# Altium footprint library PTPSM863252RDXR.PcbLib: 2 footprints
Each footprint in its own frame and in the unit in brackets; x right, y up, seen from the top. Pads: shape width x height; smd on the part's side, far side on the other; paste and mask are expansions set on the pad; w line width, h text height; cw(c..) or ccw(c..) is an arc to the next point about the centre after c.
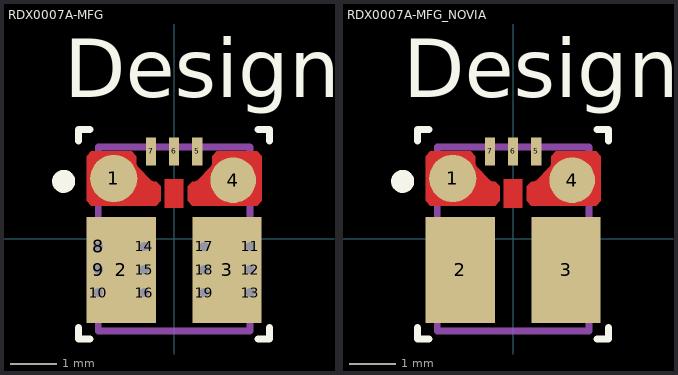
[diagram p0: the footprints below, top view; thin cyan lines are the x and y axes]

## RDX0007A-MFG [mm]
pads (19):
  round 1.025 smd paste-0.5 mask-0.495: 1(-1.312,1.312)
  rect 1.5x2.3 smd paste-1.137 mask-1.143: 2(-1.15,-0.675) 3(1.15,-0.675)
  round 0.991 smd paste-0.483 mask-0.483: 4(1.281,1.276)
  rect 0.22x0.6 smd paste+0 mask-0.292: 5(0.5,1.9) 6(0,1.9) 7(-0.5,1.9)
  round 0.5 hole 0.203 paste-0.25 mask-0.241: 8(-1.65,-0.165) 9(-1.65,-0.665) 10(-1.65,-1.165) 11(1.65,-0.165) 12(1.65,-0.665) 13(1.65,-1.165) 14(-0.65,-0.165) 15(-0.65,-0.665) 16(-0.65,-1.165) 17(0.65,-0.165) 18(0.65,-0.665) 19(0.65,-1.165)
Top Layer:
  region: -0.2,1.295 -0.2,0.675 0.2,0.675 0.2,1.295
  region: 1.9,0.825 1.9,1.8 1.8,1.9 0.925,1.9 0.825,1.8 0.825,1.634 0.796,1.563 0.507,1.274 0.436,1.245 0.39,1.245 0.29,1.145 0.29,0.825 0.39,0.725 1.8,0.725
  region: -1.9,0.825 -1.9,1.8 -1.8,1.9 -0.925,1.9 -0.825,1.8 -0.825,1.634 -0.796,1.563 -0.507,1.274 -0.436,1.245 -0.39,1.245 -0.29,1.145 -0.29,0.825 -0.39,0.725 -1.8,0.725
Top Overlay:
  circle w0.25: c-2.4,1.25 r0.125
  lines w0.15: -2.075,-1.925 -2.075,-2.175 -1.825,-2.175 ; -2.075,2.125 -2.075,2.375 -1.825,2.375 ; 1.825,-2.175 2.075,-2.175 2.075,-1.925 ; 1.825,2.375 2.075,2.375 2.075,2.125
  text "Designator1027" at -2.388,3.073 h1.27
  text ".Designator" at -3.492,-0.635 h1.27
Top Paste:
  drawing of 8 lines, arcs and shapes, not listed
Top Solder:
  drawing of 7 lines, arcs and shapes, not listed
Mechanical 13:
  lines w0.15: -1.65,-2 -1.65,2 1.65,2 1.65,-2 -1.65,-2
  text ".Designator" at -3.492,-0.635 h1.27

## RDX0007A-MFG_NOVIA [mm]
pads (7):
  round 1.025 smd paste-0.5 mask-0.495: 1(-1.312,1.312)
  rect 1.5x2.3 smd paste-1.137 mask-1.143: 2(-1.15,-0.675) 3(1.15,-0.675)
  round 0.991 smd paste-0.483 mask-0.483: 4(1.281,1.276)
  rect 0.22x0.6 smd paste+0 mask-0.292: 5(0.5,1.9) 6(0,1.9) 7(-0.5,1.9)
Top Layer:
  region: -0.2,1.295 -0.2,0.675 0.2,0.675 0.2,1.295
  region: -1.9,0.825 -1.9,1.8 -1.8,1.9 -0.925,1.9 -0.825,1.8 -0.825,1.634 -0.796,1.563 -0.507,1.274 -0.436,1.245 -0.39,1.245 -0.29,1.145 -0.29,0.825 -0.39,0.725 -1.8,0.725
  region: 1.9,0.825 1.9,1.8 1.8,1.9 0.925,1.9 0.825,1.8 0.825,1.634 0.796,1.563 0.507,1.274 0.436,1.245 0.39,1.245 0.29,1.145 0.29,0.825 0.39,0.725 1.8,0.725
Top Overlay:
  circle w0.25: c-2.4,1.25 r0.125
  lines w0.15: -2.075,-1.925 -2.075,-2.175 -1.825,-2.175 ; -2.075,2.125 -2.075,2.375 -1.825,2.375 ; 1.825,-2.175 2.075,-2.175 2.075,-1.925 ; 1.825,2.375 2.075,2.375 2.075,2.125
  text "Designator1026" at -2.388,3.073 h1.27
  text ".Designator" at -3.492,-0.635 h1.27
Top Paste:
  drawing of 8 lines, arcs and shapes, not listed
Top Solder:
  drawing of 7 lines, arcs and shapes, not listed
Mechanical 13:
  lines w0.15: -1.65,-2 1.65,-2 1.65,2 -1.65,2 -1.65,-2
  text ".Designator" at -3.492,-0.635 h1.27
